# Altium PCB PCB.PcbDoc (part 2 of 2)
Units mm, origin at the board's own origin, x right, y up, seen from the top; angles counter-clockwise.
Board outline 69.72 x 25.78 mm, 2 copper layers (Top Layer, Bottom Layer); 68 components, 49 nets, 251 pads, 101 vias.
Unrouted connection lines stored in the file: 33.
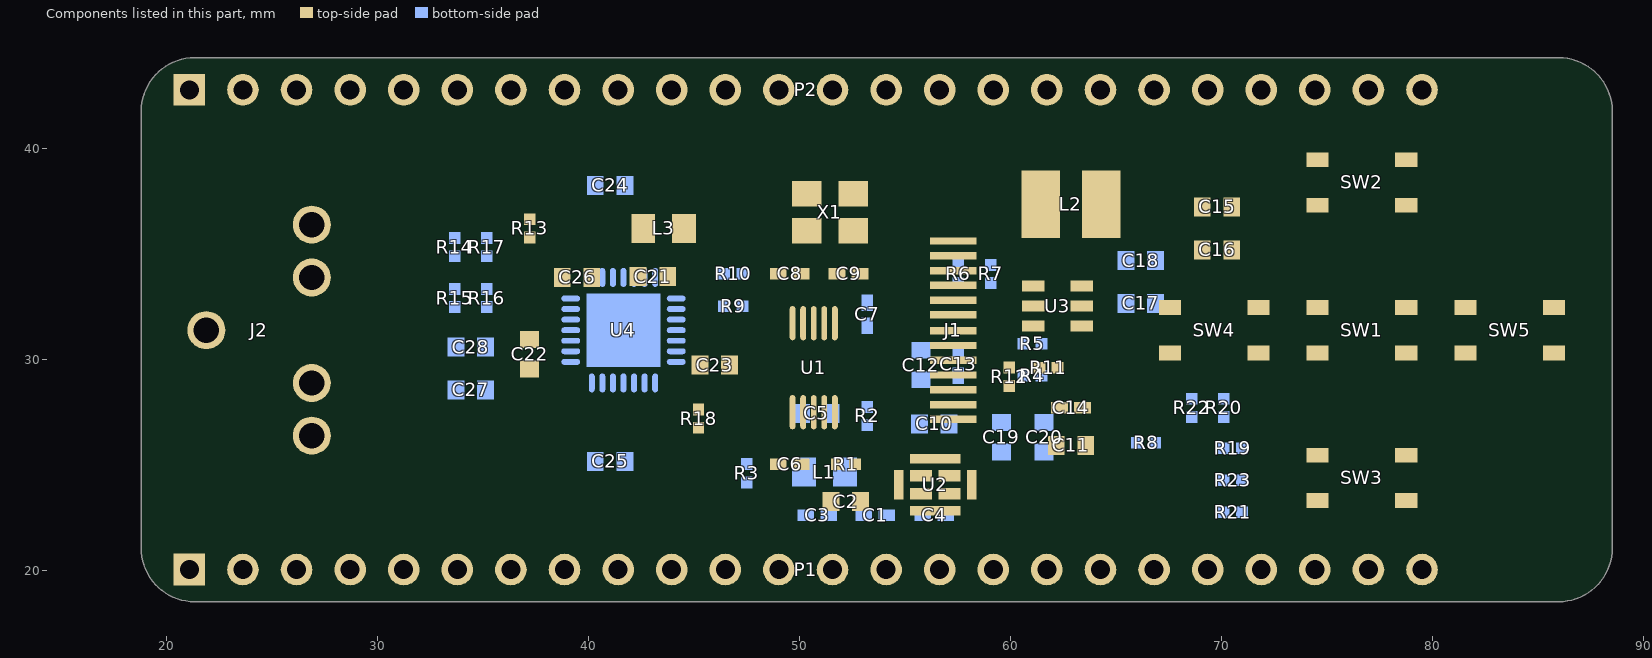
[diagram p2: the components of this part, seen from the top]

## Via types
v1: diameter 0.4, hole 0.25, Top Layer to Bottom Layer, tented both sides, 100 vias
v2: diameter 0.4/0.4 (per signal layer), hole 0.25, Top Layer to Bottom Layer, tented both sides, 1 vias

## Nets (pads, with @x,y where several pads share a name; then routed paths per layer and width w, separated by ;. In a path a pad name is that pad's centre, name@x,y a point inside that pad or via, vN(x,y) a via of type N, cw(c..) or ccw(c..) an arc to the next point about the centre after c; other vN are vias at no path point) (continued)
copper on no net: | length 39.2
  Top Layer w0.013: 84.36,21.761 cw(c84.362,21.776) 84.347,21.776 84.347,22.06 cw(c84.362,22.06) 84.36,22.075 84.638,22.129 ccw(c84.635,22.143) 84.649,22.138 84.746,22.371 ccw(c84.732,22.377) 84.745,22.385 84.585,22.62 cw(c84.598,22.629) 84.587,22.639 84.788,22.84 cw(c84.799,22.829) 84.807,22.842 85.042,22.683 ccw(c85.051,22.695) 85.056,22.681 85.29,22.778 ccw(c85.284,22.792) 85.299,22.789 85.353,23.068 cw(c85.367,23.065) 85.367,23.08 85.651,23.08 cw(c85.651,23.065) 85.666,23.068 85.72,22.789 ccw(c85.735,22.792) 85.729,22.778 85.962,22.681 ccw(c85.968,22.695) 85.976,22.683 86.211,22.842 cw(c86.22,22.829) 86.23,22.84 86.431,22.639 cw(c86.421,22.629) 86.433,22.62 86.274,22.385 ccw(c86.287,22.377) 86.273,22.371 86.369,22.138 ccw(c86.383,22.143) 86.38,22.129 86.659,22.075 cw(c86.656,22.06) 86.671,22.06 86.671,21.776 cw(c86.656,21.776) 86.659,21.761 ; 84.36,21.761 84.638,21.708 cw(c84.635,21.693) 84.649,21.699 84.746,21.465 cw(c84.732,21.459) 84.745,21.451 84.585,21.216 ccw(c84.598,21.208) 84.587,21.197 84.788,20.996 ccw(c84.799,21.007) 84.807,20.994 85.042,21.153 cw(c85.051,21.141) 85.056,21.155 85.163,21.11 ccw(c85.169,21.124) 85.183,21.119 85.38,21.601 ccw(c85.366,21.606) 85.372,21.62 cw(c85.509,21.918) 85.647,21.62 ccw(c85.653,21.606) 85.639,21.601 85.836,21.119 ccw(c85.85,21.124) 85.855,21.11 85.962,21.155 cw(c85.968,21.141) 85.976,21.153 86.211,20.994 ccw(c86.22,21.007) 86.23,20.996 86.431,21.197 ccw(c86.421,21.208) 86.433,21.216 86.274,21.451 cw(c86.287,21.459) 86.273,21.465 86.369,21.699 cw(c86.383,21.693) 86.38,21.708 86.659,21.761 ; 84.386,20.209 84.386,20.458 ccw(c84.493,20.567) 84.423,20.432 ccw(c84.465,20.517) 84.466,20.422 ccw(c84.467,20.541) 84.493,20.425 ccw(c84.473,20.511) 84.515,20.433 ccw(c84.465,20.527) 84.549,20.462 ccw(c84.476,20.518) 84.567,20.501 ccw(c84.341,20.542) 84.57,20.532 ccw(c83.711,20.577) 84.571,20.58 ccw(c83.703,20.584) 84.57,20.629 ccw(c84.343,20.62) 84.567,20.66 ccw(c84.474,20.642) 84.549,20.699 ccw(c84.462,20.631) 84.515,20.728 ccw(c84.473,20.652) 84.493,20.737 ccw(c84.467,20.624) 84.466,20.739 ccw(c84.465,20.634) 84.422,20.73 ccw(c84.468,20.631) 84.386,20.703 84.386,20.736 84.323,20.736 84.323,19.932 84.386,19.932 84.386,20.117 cw(c84.469,20.118) 84.39,20.144 cw(c84.444,20.126) 84.403,20.166 cw(c84.445,20.125) 84.423,20.179 cw(c84.447,20.118) 84.448,20.183 cw(c84.448,20.12) 84.472,20.179 cw(c84.45,20.125) 84.491,20.166 cw(c84.451,20.126) 84.504,20.144 cw(c84.426,20.118) 84.509,20.117 84.509,19.932 84.571,19.932 84.571,20.138 ccw(c84.433,20.139) 84.569,20.163 ccw(c84.467,20.145) 84.563,20.184 ccw(c84.484,20.151) 84.538,20.218 ccw(c84.455,20.119) 84.503,20.239 ccw(c84.468,20.149) 84.468,20.246 ccw(c84.466,20.136) 84.422,20.236 ccw(c84.461,20.152) 84.387,20.209 ; 84.991,20.703 84.991,20.736 84.928,20.736 84.928,20.426 84.991,20.426 84.991,20.61 cw(c85.074,20.612) 84.995,20.638 cw(c85.048,20.62) 85.008,20.659 cw(c85.05,20.619) 85.028,20.673 cw(c85.052,20.611) 85.052,20.677 cw(c85.053,20.614) 85.076,20.673 cw(c85.054,20.619) 85.096,20.659 cw(c85.056,20.62) 85.109,20.638 cw(c85.031,20.612) 85.114,20.61 85.114,20.426 85.176,20.426 85.176,20.632 ccw(c85.037,20.633) 85.174,20.657 ccw(c85.072,20.639) 85.168,20.678 ccw(c85.088,20.645) 85.142,20.712 ccw(c85.059,20.613) 85.108,20.733 ccw(c85.072,20.643) 85.073,20.739 ccw(c85.071,20.629) 85.027,20.73 ccw(c85.065,20.645) 84.992,20.703 ; 85.001,20.209 85.001,20.242 84.939,20.242 84.939,19.932 85.001,19.932 85.001,20.118 cw(c85.085,20.12) 85.006,20.148 cw(c85.05,20.132) 85.02,20.168 cw(c85.062,20.119) 85.062,20.183 cw(c85.062,20.124) 85.083,20.179 cw(c85.053,20.103) 85.103,20.168 85.148,20.222 ccw(c85.075,20.13) 85.117,20.24 ccw(c85.083,20.15) 85.083,20.246 ccw(c85.081,20.136) 85.037,20.236 ccw(c85.076,20.152) 85.003,20.209 ; 85.563,20.025 85.503,20.242 85.437,20.242 85.537,19.932 85.592,19.932 85.657,20.149 ; 85.564,20.025 85.634,20.242 85.68,20.242 85.75,20.025 85.751,20.025 85.811,20.242 85.877,20.242 85.778,19.932 85.723,19.932 85.658,20.149 ; 86.267,20.209 86.267,20.242 86.205,20.242 86.205,19.932 86.267,19.932 86.267,20.118 cw(c86.35,20.12) 86.272,20.148 cw(c86.316,20.132) 86.286,20.168 cw(c86.327,20.119) 86.327,20.183 cw(c86.327,20.124) 86.348,20.179 cw(c86.319,20.103) 86.369,20.168 86.414,20.222 ccw(c86.34,20.13) 86.382,20.24 ccw(c86.349,20.15) 86.349,20.246 ccw(c86.347,20.136) 86.303,20.236 ccw(c86.342,20.152) 86.268,20.209 ; 86.346,20.703 86.346,20.736 86.284,20.736 86.284,20.426 86.346,20.426 86.346,20.612 cw(c86.429,20.614) 86.351,20.642 cw(c86.395,20.626) 86.365,20.662 cw(c86.406,20.613) 86.406,20.677 cw(c86.406,20.618) 86.427,20.673 cw(c86.398,20.597) 86.448,20.662 86.493,20.715 ccw(c86.419,20.623) 86.461,20.733 ccw(c86.428,20.644) 86.428,20.739 ccw(c86.426,20.629) 86.382,20.73 ccw(c86.421,20.645) 86.347,20.703 ; 84.011,20.581 ccw(c84.447,20.578) 84.012,20.537 ccw(c84.17,20.55) 84.018,20.506 ccw(c84.132,20.542) 84.044,20.461 ccw(c84.124,20.533) 84.059,20.448 ccw(c84.16,20.582) 84.079,20.435 ccw(c84.124,20.517) 84.106,20.425 ccw(c84.137,20.581) 84.139,20.422 ccw(c84.14,20.578) 84.171,20.425 ccw(c84.152,20.518) 84.197,20.435 ccw(c84.116,20.584) 84.217,20.448 ccw(c84.153,20.535) 84.233,20.461 ccw(c84.145,20.542) 84.258,20.506 ccw(c84.106,20.55) 84.264,20.537 ccw(c83.826,20.578) 84.266,20.581 ccw(c83.84,20.584) 84.264,20.625 ccw(c84.106,20.611) 84.258,20.655 ccw(c84.145,20.619) 84.233,20.7 ccw(c84.149,20.622) 84.217,20.713 ccw(c84.108,20.566) 84.197,20.727 ccw(c84.152,20.645) 84.171,20.736 ccw(c84.14,20.587) 84.139,20.739 ccw(c84.137,20.584) 84.106,20.736 ccw(c84.124,20.646) 84.079,20.727 ccw(c84.168,20.569) 84.059,20.713 ccw(c84.127,20.624) 84.044,20.7 ccw(c84.132,20.619) 84.018,20.655 ccw(c84.169,20.611) 84.012,20.625 ccw(c84.433,20.584) 84.011,20.581 ; 84.073,20.581 ccw(c84.527,20.579) 84.074,20.552 ccw(c84.201,20.558) 84.076,20.533 ccw(c84.145,20.549) 84.088,20.507 ccw(c84.129,20.535) 84.109,20.49 ccw(c84.137,20.555) 84.139,20.484 ccw(c84.14,20.555) 84.168,20.49 ccw(c84.147,20.536) 84.189,20.507 ccw(c84.124,20.552) 84.201,20.533 ccw(c84.088,20.558) 84.203,20.552 ccw(c83.798,20.578) 84.204,20.58 ccw(c83.795,20.583) 84.203,20.609 ccw(c84.088,20.603) 84.201,20.628 ccw(c84.121,20.608) 84.189,20.654 ccw(c84.147,20.625) 84.168,20.671 ccw(c84.14,20.606) 84.139,20.677 ccw(c84.137,20.606) 84.109,20.671 ccw(c84.129,20.626) 84.088,20.654 ccw(c84.147,20.611) 84.076,20.628 ccw(c84.198,20.603) 84.074,20.609 ccw(c84.504,20.583) 84.073,20.581 ; 84.386,20.58 ccw(c84.628,20.58) 84.395,20.515 ccw(c84.431,20.525) 84.412,20.492 ccw(c84.438,20.537) 84.427,20.486 ccw(c84.446,20.575) 84.447,20.484 ccw(c84.448,20.579) 84.467,20.486 ccw(c84.456,20.538) 84.482,20.492 ccw(c84.464,20.524) 84.5,20.514 ccw(c84.274,20.578) 84.509,20.58 ccw(c84.272,20.583) 84.5,20.647 ccw(c84.464,20.637) 84.482,20.669 ccw(c84.456,20.623) 84.467,20.675 ccw(c84.448,20.583) 84.447,20.677 ccw(c84.446,20.586) 84.427,20.675 ccw(c84.438,20.624) 84.412,20.669 ccw(c84.432,20.636) 84.395,20.646 ccw(c84.63,20.581) 84.386,20.58 ; 84.618,20.579 cw(c84.932,20.581) 84.621,20.621 cw(c84.813,20.597) 84.628,20.656 cw(c84.746,20.618) 84.641,20.684 cw(c84.718,20.636) 84.659,20.705 cw(c84.762,20.585) 84.702,20.731 cw(c84.746,20.621) 84.746,20.739 cw(c84.747,20.611) 84.794,20.731 cw(c84.744,20.607) 84.835,20.704 cw(c84.759,20.62) 84.864,20.662 cw(c84.73,20.611) 84.874,20.608 84.874,20.557 84.68,20.557 ccw(c84.779,20.555) 84.686,20.524 ccw(c84.742,20.543) 84.701,20.5 ccw(c84.748,20.551) 84.725,20.485 ccw(c84.753,20.567) 84.754,20.481 ccw(c84.755,20.57) 84.791,20.488 ccw(c84.748,20.582) 84.822,20.51 84.868,20.472 cw(c84.753,20.569) 84.843,20.449 cw(c84.771,20.546) 84.816,20.433 cw(c84.756,20.583) 84.755,20.422 cw(c84.756,20.57) 84.708,20.43 cw(c84.767,20.602) 84.663,20.453 cw(c84.708,20.518) 84.643,20.472 cw(c84.734,20.536) 84.629,20.5 cw(c84.803,20.56) 84.621,20.536 cw(c84.933,20.578) 84.618,20.579 ; 84.624,20.022 cw(c84.724,20.023) 84.63,20.057 cw(c84.713,20.026) 84.649,20.087 cw(c84.706,20.033) 84.68,20.107 cw(c84.721,19.986) 84.722,20.114 84.806,20.114 84.806,20.147 ccw(c84.767,20.148) 84.802,20.165 ccw(c84.774,20.15) 84.791,20.177 ccw(c84.762,20.13) 84.771,20.185 ccw(c84.748,20.06) 84.744,20.187 ccw(c84.743,20.04) 84.724,20.186 ccw(c84.735,20.1) 84.708,20.182 ccw(c84.726,20.141) 84.687,20.163 84.639,20.2 cw(c84.726,20.137) 84.682,20.235 cw(c84.731,20.124) 84.71,20.243 cw(c84.738,20.084) 84.741,20.245 cw(c84.746,20.038) 84.792,20.24 cw(c84.764,20.117) 84.832,20.223 cw(c84.79,20.163) 84.858,20.191 cw(c84.762,20.151) 84.864,20.169 cw(c84.712,20.142) 84.867,20.143 84.867,19.931 84.806,19.931 84.806,19.958 84.805,19.958 cw(c84.76,19.981) 84.779,19.935 cw(c84.744,20.022) 84.758,19.929 cw(c84.732,20.1) 84.73,19.927 cw(c84.731,20.072) 84.685,19.934 cw(c84.713,20.015) 84.653,19.954 cw(c84.711,20.019) 84.631,19.984 cw(c84.718,20.02) 84.624,20.022 ; 84.68,20.608 cw(c84.78,20.607) 84.686,20.639 cw(c84.744,20.619) 84.7,20.662 cw(c84.743,20.62) 84.721,20.676 cw(c84.745,20.613) 84.746,20.681 cw(c84.747,20.615) 84.771,20.676 cw(c84.748,20.62) 84.792,20.662 cw(c84.747,20.618) 84.806,20.639 cw(c84.71,20.606) 84.811,20.608 84.68,20.608 ; 84.681,20.025 ccw(c84.713,20.024) 84.684,20.01 ccw(c84.72,20.029) 84.695,19.998 ccw(c84.722,20.029) 84.712,19.989 ccw(c84.736,20.083) 84.738,19.986 ccw(c84.743,20.164) 84.771,19.988 ccw(c84.763,20.046) 84.792,19.995 ccw(c84.778,20.014) 84.798,20.001 ccw(c84.766,20.022) 84.803,20.011 ccw(c84.71,20.037) 84.806,20.04 84.806,20.062 84.733,20.062 ccw(c84.735,19.956) 84.71,20.059 ccw(c84.721,20.012) 84.694,20.052 ccw(c84.711,20.028) 84.684,20.041 ccw(c84.717,20.026) 84.681,20.025 ; 85.152,20.087 cw(c86.03,20.091) 85.153,20.135 cw(c85.386,20.126) 85.157,20.166 cw(c85.246,20.149) 85.174,20.205 cw(c85.258,20.141) 85.208,20.234 cw(c85.25,20.158) 85.231,20.243 cw(c85.256,20.128) 85.257,20.246 cw(c85.259,20.154) 85.301,20.235 cw(c85.223,20.089) 85.337,20.209 85.337,20.367 85.4,20.367 85.4,19.932 85.337,19.932 85.337,19.964 cw(c85.255,20.037) 85.301,19.937 cw(c85.258,20.034) 85.257,19.928 cw(c85.256,20.049) 85.231,19.931 cw(c85.25,20.017) 85.208,19.939 cw(c85.255,20.029) 85.174,19.968 cw(c85.244,20.023) 85.157,20.007 cw(c85.392,20.048) 85.153,20.038 cw(c86.053,20.083) 85.152,20.087 ; 85.215,20.087 ccw(c85.452,20.085) 85.223,20.02 ccw(c85.259,20.03) 85.241,19.998 ccw(c85.267,20.045) 85.256,19.992 ccw(c85.275,20.086) 85.276,19.99 ccw(c85.277,20.079) 85.296,19.992 ccw(c85.285,20.042) 85.311,19.998 ccw(c85.291,20.031) 85.329,20.022 ccw(c85.096,20.086) 85.337,20.087 ccw(c85.1,20.088) 85.329,20.152 ccw(c85.291,20.142) 85.311,20.175 ccw(c85.285,20.131) 85.296,20.181 ccw(c85.277,20.094) 85.276,20.183 ccw(c85.275,20.088) 85.256,20.181 ccw(c85.267,20.129) 85.241,20.176 ccw(c85.259,20.143) 85.223,20.153 ccw(c85.448,20.089) 85.215,20.087 ; 85.349,20.477 ccw(c85.491,20.627) 85.412,20.436 ccw(c85.484,20.615) 85.485,20.422 ccw(c85.487,20.611) 85.535,20.428 ccw(c85.499,20.565) 85.577,20.447 ccw(c85.532,20.516) 85.605,20.477 ccw(c85.529,20.516) 85.614,20.517 ccw(c85.506,20.518) 85.609,20.552 ccw(c85.519,20.522) 85.593,20.581 ccw(c85.539,20.537) 85.565,20.601 ccw(c85.524,20.505) 85.546,20.607 ccw(c85.514,20.457) 85.524,20.61 85.473,20.614 cw(c85.477,20.7) 85.453,20.617 cw(c85.461,20.647) 85.44,20.624 cw(c85.462,20.647) 85.434,20.633 cw(c85.455,20.643) 85.432,20.643 cw(c85.466,20.644) 85.443,20.67 cw(c85.467,20.641) 85.459,20.678 cw(c85.483,20.577) 85.485,20.681 cw(c85.487,20.564) 85.53,20.673 cw(c85.45,20.48) 85.568,20.652 85.606,20.697 ccw(c85.486,20.553) 85.554,20.728 ccw(c85.498,20.583) 85.522,20.737 ccw(c85.486,20.507) 85.485,20.739 ccw(c85.483,20.579) 85.439,20.733 ccw(c85.473,20.619) 85.402,20.715 ccw(c85.447,20.653) 85.377,20.685 ccw(c85.467,20.646) 85.369,20.644 ccw(c85.463,20.642) 85.375,20.608 ccw(c85.441,20.635) 85.395,20.581 ccw(c85.459,20.654) 85.423,20.564 ccw(c85.466,20.675) 85.459,20.556 85.513,20.551 cw(c85.508,20.476) 85.53,20.548 cw(c85.519,20.512) 85.542,20.542 cw(c85.527,20.522) 85.549,20.532 cw(c85.522,20.521) 85.551,20.52 cw(c85.518,20.52) 85.547,20.503 cw(c85.517,20.521) 85.534,20.491 cw(c85.499,20.552) 85.514,20.483 cw(c85.491,20.589) 85.49,20.481 cw(c85.489,20.62) 85.437,20.49 cw(c85.49,20.619) 85.392,20.52 85.349,20.477 ; 85.653,20.581 ccw(c86.089,20.578) 85.654,20.537 ccw(c85.812,20.55) 85.66,20.506 ccw(c85.774,20.542) 85.686,20.461 ccw(c85.766,20.533) 85.701,20.448 ccw(c85.802,20.582) 85.721,20.435 ccw(c85.766,20.517) 85.748,20.425 ccw(c85.779,20.581) 85.78,20.422 ccw(c85.782,20.578) 85.813,20.425 ccw(c85.794,20.518) 85.839,20.435 ccw(c85.758,20.584) 85.859,20.448 ccw(c85.795,20.535) 85.875,20.461 ccw(c85.787,20.542) 85.9,20.506 ccw(c85.748,20.55) 85.906,20.537 ccw(c85.468,20.578) 85.908,20.581 ccw(c85.482,20.584) 85.906,20.625 ccw(c85.748,20.611) 85.9,20.655 ccw(c85.787,20.619) 85.875,20.7 ccw(c85.791,20.622) 85.859,20.713 ccw(c85.75,20.566) 85.839,20.727 ccw(c85.794,20.645) 85.813,20.736 ccw(c85.782,20.587) 85.78,20.739 ccw(c85.779,20.584) 85.748,20.736 ccw(c85.766,20.646) 85.721,20.727 ccw(c85.81,20.569) 85.701,20.713 ccw(c85.769,20.624) 85.686,20.7 ccw(c85.774,20.619) 85.66,20.655 ccw(c85.811,20.611) 85.654,20.625 ccw(c86.075,20.584) 85.653,20.581 ; 85.715,20.581 ccw(c86.169,20.579) 85.716,20.552 ccw(c85.843,20.558) 85.718,20.533 ccw(c85.787,20.549) 85.73,20.507 ccw(c85.771,20.535) 85.751,20.49 ccw(c85.779,20.555) 85.78,20.484 ccw(c85.782,20.555) 85.81,20.49 ccw(c85.789,20.536) 85.831,20.507 ccw(c85.766,20.552) 85.843,20.533 ccw(c85.73,20.558) 85.845,20.552 ccw(c85.44,20.578) 85.846,20.58 ccw(c85.437,20.583) 85.845,20.609 ccw(c85.73,20.603) 85.843,20.628 ccw(c85.763,20.608) 85.831,20.654 ccw(c85.789,20.625) 85.81,20.671 ccw(c85.782,20.606) 85.78,20.677 ccw(c85.779,20.606) 85.751,20.671 ccw(c85.771,20.626) 85.73,20.654 ccw(c85.789,20.611) 85.718,20.628 ccw(c85.84,20.603) 85.716,20.609 ccw(c86.146,20.583) 85.715,20.581 ; 85.889,20.022 cw(c85.989,20.023) 85.895,20.057 cw(c85.978,20.026) 85.914,20.087 cw(c85.97,20.033) 85.944,20.107 cw(c85.986,19.986) 85.987,20.114 86.071,20.114 86.071,20.147 ccw(c86.032,20.148) 86.067,20.165 ccw(c86.038,20.15) 86.055,20.177 ccw(c86.026,20.13) 86.036,20.185 ccw(c86.013,20.06) 86.009,20.187 ccw(c86.008,20.04) 85.989,20.186 ccw(c86,20.1) 85.973,20.182 ccw(c85.99,20.141) 85.952,20.163 85.904,20.2 cw(c85.99,20.137) 85.947,20.235 cw(c85.995,20.124) 85.974,20.243 cw(c86.002,20.084) 86.006,20.245 cw(c86.01,20.038) 86.057,20.24 cw(c86.028,20.117) 86.097,20.223 cw(c86.054,20.163) 86.122,20.191 cw(c86.026,20.151) 86.129,20.169 cw(c85.977,20.142) 86.131,20.143 86.131,19.931 86.071,19.931 86.071,19.958 86.069,19.958 cw(c86.025,19.981) 86.043,19.935 cw(c86.008,20.022) 86.022,19.929 cw(c85.996,20.1) 85.995,19.927 cw(c85.996,20.072) 85.95,19.934 cw(c85.977,20.015) 85.917,19.954 cw(c85.976,20.019) 85.896,19.984 cw(c85.983,20.02) 85.889,20.022 ; 85.945,20.025 ccw(c85.977,20.024) 85.949,20.01 ccw(c85.984,20.029) 85.959,19.998 ccw(c85.987,20.029) 85.977,19.989 ccw(c86.001,20.083) 86.003,19.986 ccw(c86.008,20.164) 86.035,19.988 ccw(c86.027,20.046) 86.056,19.995 ccw(c86.043,20.014) 86.063,20.001 ccw(c86.031,20.022) 86.067,20.011 ccw(c85.975,20.037) 86.071,20.04 86.071,20.062 85.998,20.062 ccw(c86,19.956) 85.975,20.059 ccw(c85.986,20.012) 85.958,20.052 ccw(c85.975,20.028) 85.948,20.041 ccw(c85.981,20.026) 85.945,20.025 ; 85.965,20.53 ccw(c86.105,20.529) 85.967,20.505 ccw(c86.069,20.523) 85.973,20.483 ccw(c86.052,20.516) 85.999,20.449 ccw(c86.08,20.548) 86.033,20.429 ccw(c86.069,20.521) 86.069,20.422 ccw(c86.071,20.531) 86.115,20.431 ccw(c86.076,20.516) 86.149,20.458 86.15,20.458 86.15,20.426 86.213,20.426 86.213,20.736 86.15,20.736 86.15,20.551 cw(c86.067,20.549) 86.146,20.523 cw(c86.093,20.541) 86.133,20.502 cw(c86.091,20.543) 86.113,20.488 cw(c86.09,20.548) 86.089,20.484 cw(c86.088,20.55) 86.065,20.488 cw(c86.086,20.542) 86.045,20.502 cw(c86.084,20.541) 86.032,20.523 cw(c86.111,20.549) 86.027,20.551 86.027,20.736 85.965,20.736 85.965,20.53 ; 86.418,20.086 cw(c86.731,20.087) 86.42,20.127 cw(c86.612,20.103) 86.428,20.162 cw(c86.546,20.125) 86.441,20.19 cw(c86.517,20.142) 86.459,20.211 cw(c86.561,20.092) 86.501,20.237 cw(c86.546,20.128) 86.546,20.246 cw(c86.547,20.117) 86.593,20.237 cw(c86.544,20.113) 86.635,20.21 cw(c86.558,20.126) 86.664,20.169 cw(c86.529,20.117) 86.673,20.115 86.673,20.063 86.48,20.063 ccw(c86.578,20.061) 86.485,20.03 ccw(c86.541,20.049) 86.501,20.006 ccw(c86.548,20.057) 86.525,19.991 ccw(c86.553,20.073) 86.554,19.987 ccw(c86.554,20.076) 86.59,19.994 ccw(c86.548,20.088) 86.622,20.017 86.667,19.978 cw(c86.553,20.075) 86.643,19.955 cw(c86.57,20.052) 86.615,19.94 cw(c86.556,20.09) 86.555,19.928 cw(c86.555,20.076) 86.508,19.936 cw(c86.567,20.108) 86.462,19.959 cw(c86.508,20.024) 86.443,19.979 cw(c86.534,20.042) 86.429,20.006 cw(c86.603,20.066) 86.42,20.042 cw(c86.733,20.084) 86.418,20.086 ; 86.48,20.115 cw(c86.579,20.113) 86.485,20.146 cw(c86.543,20.125) 86.499,20.168 cw(c86.543,20.126) 86.52,20.182 cw(c86.545,20.119) 86.546,20.187 cw(c86.546,20.121) 86.571,20.182 cw(c86.548,20.126) 86.591,20.168 cw(c86.546,20.125) 86.605,20.146 cw(c86.51,20.112) 86.611,20.115 86.48,20.115 ; 86.487,20.58 cw(c86.757,20.582) 86.489,20.62 cw(c86.666,20.595) 86.498,20.653 cw(c86.616,20.612) 86.511,20.681 cw(c86.597,20.624) 86.53,20.703 cw(c86.633,20.584) 86.576,20.73 cw(c86.627,20.596) 86.627,20.739 cw(c86.628,20.597) 86.661,20.736 cw(c86.633,20.617) 86.691,20.724 cw(c86.608,20.572) 86.739,20.686 86.693,20.645 ccw(c86.621,20.588) 86.664,20.669 ccw(c86.63,20.603) 86.63,20.677 ccw(c86.628,20.582) 86.594,20.671 ccw(c86.617,20.613) 86.569,20.653 ccw(c86.631,20.603) 86.554,20.623 ccw(c86.708,20.583) 86.549,20.58 ccw(c86.706,20.578) 86.554,20.538 ccw(c86.631,20.558) 86.569,20.508 ccw(c86.617,20.548) 86.594,20.49 ccw(c86.628,20.579) 86.63,20.484 ccw(c86.63,20.558) 86.664,20.492 ccw(c86.621,20.572) 86.693,20.517 86.739,20.475 cw(c86.61,20.588) 86.691,20.437 cw(c86.633,20.545) 86.661,20.426 cw(c86.628,20.566) 86.627,20.422 cw(c86.627,20.566) 86.576,20.431 cw(c86.633,20.578) 86.53,20.459 cw(c86.595,20.536) 86.511,20.48 cw(c86.615,20.548) 86.498,20.507 cw(c86.665,20.566) 86.489,20.541 cw(c86.756,20.579) 86.487,20.58 ; 86.757,20.579 cw(c87.071,20.581) 86.76,20.621 cw(c86.952,20.597) 86.768,20.656 cw(c86.885,20.618) 86.781,20.684 cw(c86.857,20.636) 86.799,20.705 cw(c86.901,20.585) 86.841,20.731 cw(c86.885,20.621) 86.885,20.739 cw(c86.886,20.611) 86.933,20.731 cw(c86.883,20.607) 86.975,20.704 cw(c86.898,20.62) 87.003,20.662 cw(c86.869,20.611) 87.013,20.608 87.013,20.557 86.82,20.557 ccw(c86.918,20.555) 86.825,20.524 ccw(c86.881,20.543) 86.84,20.5 ccw(c86.888,20.551) 86.864,20.485 ccw(c86.893,20.567) 86.894,20.481 ccw(c86.894,20.57) 86.93,20.488 ccw(c86.887,20.582) 86.962,20.51 87.007,20.472 cw(c86.893,20.569) 86.982,20.449 cw(c86.91,20.546) 86.955,20.433 cw(c86.895,20.583) 86.895,20.422 cw(c86.895,20.57) 86.848,20.43 cw(c86.907,20.602) 86.802,20.453 cw(c86.848,20.518) 86.783,20.472 cw(c86.874,20.536) 86.769,20.5 cw(c86.943,20.56) 86.76,20.536 cw(c87.072,20.578) 86.757,20.579 ; 86.82,20.608 cw(c86.919,20.607) 86.825,20.639 cw(c86.883,20.619) 86.839,20.662 cw(c86.883,20.62) 86.86,20.676 cw(c86.884,20.613) 86.885,20.681 cw(c86.886,20.615) 86.91,20.676 cw(c86.887,20.62) 86.931,20.662 cw(c86.886,20.618) 86.945,20.639 cw(c86.849,20.606) 86.951,20.608 86.82,20.608

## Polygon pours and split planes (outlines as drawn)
no net on Top Overlay "NONET_L-01_P-001" (solid): 84.004,40.31 84.074,40.195 84.155,40.087 84.245,39.988 84.344,39.897 84.452,39.817 84.567,39.747 84.689,39.688 84.818,39.641 84.952,39.607 85.091,39.585 85.234,39.578 85.377,39.585 85.515,39.607 85.649,39.641 85.778,39.688 85.9,39.747 86.015,39.817 86.123,39.897 86.222,39.988 86.313,40.087 86.393,40.195 86.463,40.31 86.522,40.432 86.569,40.561 86.603,40.695 86.625,40.833 86.632,40.976 86.625,41.119 86.603,41.258 86.569,41.392 86.522,41.521 86.463,41.643 86.393,41.758 86.313,41.866 86.222,41.965 86.123,42.055 86.015,42.136 85.9,42.206 85.778,42.265 85.649,42.312 85.515,42.346 85.377,42.367 85.234,42.375 85.091,42.367 84.952,42.346 84.818,42.312 84.689,42.265 84.567,42.206 84.452,42.136 84.344,42.055 84.245,41.965 84.155,41.866 84.074,41.758 84.004,41.643 83.945,41.521 83.898,41.392 83.864,41.258 83.843,41.119 83.835,40.976 83.843,40.833 83.864,40.695 83.898,40.561 83.945,40.432
no net on Top Overlay "NONET_L-01_P-001" (none): 84.897,39.141 84.891,39.16 84.891,39.183 84.9,39.21 84.919,39.23 84.953,39.244 84.923,39.276 84.917,39.315 84.934,39.354 84.974,39.378 85.022,39.381 85.056,39.372 85.081,39.355 85.094,39.334 85.096,39.309 85.081,39.278 85.045,39.256 85.071,39.239 85.086,39.22 85.093,39.2 85.092,39.176 85.077,39.135 85.05,39.109 85.012,39.096 84.971,39.096 84.927,39.111
no net on Top Overlay "NONET_L-01_P-001" (solid): 86.591,41.848 86.604,41.856 86.598,41.868 86.595,41.88 86.596,41.892 86.604,41.901 86.673,41.945 86.679,41.937 86.655,41.869 86.625,41.796 86.681,41.708 86.694,41.717 86.689,41.725 86.685,41.736 86.686,41.758 86.693,41.782 86.711,41.836 86.728,41.883 86.753,41.865 86.777,41.856 86.801,41.856 86.825,41.867 86.845,41.888 86.851,41.915 86.844,41.949 86.823,41.989 86.74,42.117 86.728,42.109 86.733,42.096 86.737,42.082 86.736,42.069 86.727,42.061 86.567,41.957 86.555,41.953 86.543,41.957 86.534,41.966 86.525,41.978 86.512,41.97
no net on Top Overlay "NONET_L-01_P-001" (solid): 85.871,39.265 85.883,39.246 85.899,39.233 85.94,39.222 85.985,39.233 86.02,39.254 86.045,39.285 86.055,39.321 86.047,39.364 86.035,39.385 86.019,39.398 85.996,39.406 85.966,39.408 85.985,39.445 85.982,39.48 85.967,39.5 85.945,39.511 85.915,39.513 85.881,39.503 85.841,39.475 85.82,39.434 85.825,39.392 85.851,39.362 85.893,39.35 85.871,39.32 85.865,39.293
no net on Top Overlay "NONET_L-01_P-001" (none): 85.409,39.097 85.428,39.086 85.471,39.098 85.509,39.12 85.539,39.151 85.561,39.188 85.571,39.23 85.57,39.28 85.562,39.316 85.548,39.343 85.53,39.363 85.509,39.376 85.484,39.382 85.455,39.382 85.426,39.374 85.403,39.361 85.385,39.342 85.374,39.32 85.369,39.267 85.379,39.235 85.398,39.212 85.421,39.2 85.449,39.198 85.481,39.208 85.514,39.241 85.512,39.198 85.504,39.166 85.488,39.138 85.462,39.116 85.43,39.106 85.413,39.106
no net on Top Overlay "NONET_L-01_P-001" (none): 85.409,39.097 85.428,39.086 85.471,39.098 85.509,39.12 85.539,39.151 85.561,39.188 85.571,39.23 85.57,39.28 85.562,39.316 85.548,39.343 85.53,39.363 85.509,39.376 85.484,39.382 85.455,39.382 85.426,39.374 85.403,39.361 85.385,39.342 85.374,39.32 85.369,39.267 85.379,39.235 85.398,39.212 85.421,39.2 85.449,39.198 85.481,39.208 85.514,39.241 85.512,39.198 85.504,39.166 85.488,39.138 85.462,39.116 85.43,39.106 85.413,39.106
no net on Top Overlay "NONET_L-01_P-001" (solid): 83.531,40.194 83.529,40.207 83.527,40.222 83.531,40.234 83.541,40.241 83.72,40.309 83.732,40.311 83.743,40.304 83.75,40.293 83.756,40.28 83.77,40.285 83.718,40.424 83.704,40.418 83.707,40.404 83.708,40.391 83.704,40.379 83.694,40.372 83.623,40.345 83.615,40.365 83.593,40.41 83.565,40.441 83.53,40.455 83.49,40.45 83.464,40.433 83.452,40.407 83.451,40.373 83.464,40.328 83.517,40.189
no net on Top Overlay "NONET_L-01_P-001" (solid): 84.897,39.141 84.891,39.16 84.891,39.183 84.9,39.21 84.919,39.23 84.953,39.244 84.923,39.276 84.917,39.315 84.934,39.354 84.974,39.378 85.022,39.381 85.056,39.372 85.081,39.355 85.094,39.334 85.096,39.309 85.081,39.278 85.045,39.256 85.071,39.239 85.086,39.22 85.093,39.2 85.092,39.176 85.077,39.135 85.05,39.109 85.012,39.096 84.971,39.096 84.927,39.111
no net on Top Overlay "NONET_L-01_P-001" (solid): 85.409,39.097 85.428,39.086 85.471,39.098 85.509,39.12 85.539,39.151 85.561,39.188 85.571,39.23 85.57,39.28 85.562,39.316 85.548,39.343 85.53,39.363 85.509,39.376 85.484,39.382 85.455,39.382 85.426,39.374 85.403,39.361 85.385,39.342 85.374,39.32 85.369,39.267 85.379,39.235 85.398,39.212 85.421,39.2 85.449,39.198 85.481,39.208 85.514,39.241 85.512,39.198 85.504,39.166 85.488,39.138 85.462,39.116 85.43,39.106 85.413,39.106
no net on Bottom Layer "NONET_L02_P004" (none, pour order 4): 84.004,40.31 84.074,40.195 84.155,40.087 84.245,39.988 84.344,39.897 84.452,39.817 84.567,39.747 84.689,39.688 84.818,39.641 84.952,39.607 85.091,39.585 85.234,39.578 85.377,39.585 85.515,39.607 85.649,39.641 85.778,39.688 85.9,39.747 86.015,39.817 86.123,39.897 86.222,39.988 86.313,40.087 86.393,40.195 86.463,40.31 86.522,40.432 86.569,40.561 86.603,40.695 86.625,40.833 86.632,40.976 86.625,41.119 86.603,41.258 86.569,41.392 86.522,41.521 86.463,41.643 86.393,41.758 86.313,41.866 86.222,41.965 86.123,42.055 86.015,42.136 85.9,42.206 85.778,42.265 85.649,42.312 85.515,42.346 85.377,42.367 85.234,42.375 85.091,42.367 84.952,42.346 84.818,42.312 84.689,42.265 84.567,42.206 84.452,42.136 84.344,42.055 84.245,41.965 84.155,41.866 84.074,41.758 84.004,41.643 83.945,41.521 83.898,41.392 83.864,41.258 83.843,41.119 83.835,40.976 83.843,40.833 83.864,40.695 83.898,40.561 83.945,40.432
no net on Bottom Layer "NONET_L02_P005" (none, pour order 5): 84.004,40.31 84.074,40.195 84.155,40.087 84.245,39.988 84.344,39.897 84.452,39.817 84.567,39.747 84.689,39.688 84.818,39.641 84.952,39.607 85.091,39.585 85.234,39.578 85.377,39.585 85.515,39.607 85.649,39.641 85.778,39.688 85.9,39.747 86.015,39.817 86.123,39.897 86.222,39.988 86.313,40.087 86.393,40.195 86.463,40.31 86.522,40.432 86.569,40.561 86.603,40.695 86.625,40.833 86.632,40.976 86.625,41.119 86.603,41.258 86.569,41.392 86.522,41.521 86.463,41.643 86.393,41.758 86.313,41.866 86.222,41.965 86.123,42.055 86.015,42.136 85.9,42.206 85.778,42.265 85.649,42.312 85.515,42.346 85.377,42.367 85.234,42.375 85.091,42.367 84.952,42.346 84.818,42.312 84.689,42.265 84.567,42.206 84.452,42.136 84.344,42.055 84.245,41.965 84.155,41.866 84.074,41.758 84.004,41.643 83.945,41.521 83.898,41.392 83.864,41.258 83.843,41.119 83.835,40.976 83.843,40.833 83.864,40.695 83.898,40.561 83.945,40.432
GND on Bottom Layer "GND_L02_P003" (solid, remove dead copper, pour order 3): 21.336,18.542 cw(c21.336,21.082) 18.796,21.082 18.796,41.783 cw(c21.336,41.783) 21.336,44.323 85.979,44.323 cw(c85.979,41.783) 88.519,41.783 88.519,21.082 cw(c85.979,21.082) 85.979,18.542

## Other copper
Top Layer:
  region: 84.687,20.163
  region: 85.952,20.163 85.951,20.163
  region: 85.781,20.479 85.78,20.479
  region: 84.139,20.479 84.138,20.479
  region: 86.695,20.515 86.693,20.517
  region: 84.212,20.58 84.204,20.58 84.212,20.58
  region: 85.854,20.58 85.846,20.58 85.854,20.58
  region: 84.139,20.682 84.138,20.682 84.139,20.682
  region: 85.781,20.682 85.78,20.682 85.781,20.682
  region: 84.493,20.738 84.515,20.728 84.515,20.729 84.547,20.716 84.552,20.702 84.552,20.701 84.569,20.66 84.567,20.66 84.573,20.629 84.579,20.584 84.578,20.58 84.579,20.577 84.573,20.532 84.567,20.501 84.569,20.501 84.552,20.46 84.546,20.446 84.515,20.433 84.493,20.423 84.467,20.412 84.466,20.413 84.466,20.415 84.465,20.414 84.422,20.432 84.422,20.431 84.386,20.446 84.386,20.215 84.389,20.223 84.422,20.236 84.466,20.255 84.468,20.254 84.468,20.253 84.503,20.239 84.542,20.223 84.54,20.221 84.549,20.217 84.563,20.184 84.572,20.163 84.583,20.139 84.582,20.138 84.571,20.138 84.571,19.932 84.509,19.932 84.515,20.116 84.516,20.118 84.505,20.145 84.495,20.169 84.494,20.169 84.472,20.179 84.448,20.188 84.447,20.189 84.423,20.179 84.4,20.169 84.39,20.145 84.379,20.118 84.38,20.116 84.386,20.117 84.386,19.932 84.323,19.932 84.323,20.736 84.386,20.736 84.381,20.707 84.384,20.715 84.422,20.73 84.465,20.748 84.466,20.748 84.466,20.749 84.467,20.749 hole: 84.448,20.685 84.447,20.684 84.447,20.684 84.446,20.685 84.427,20.677 84.427,20.676 84.412,20.67 84.412,20.67 84.402,20.666 84.394,20.646 84.394,20.646 84.381,20.581 84.381,20.58 84.381,20.58 84.381,20.58 84.394,20.515 84.394,20.515 84.402,20.496 84.412,20.492 84.412,20.492 84.427,20.485 84.427,20.485 84.446,20.477 84.447,20.477 84.447,20.477 84.448,20.476 84.467,20.484 84.467,20.485 84.483,20.491 84.483,20.491 84.493,20.496 84.5,20.514 84.501,20.514 84.513,20.578 84.513,20.58 84.513,20.58 84.513,20.583 84.501,20.647 84.5,20.647 84.493,20.666 84.483,20.67 84.483,20.67 84.467,20.676 84.467,20.677 hole: 84.386,20.458 84.377,20.45 84.386,20.446 hole: 84.386,20.215 84.384,20.211 84.386,20.209
  region: 85.4,19.932 85.337,19.932 85.342,19.96 85.34,19.953 85.301,19.937 85.258,19.919 85.257,19.92 85.257,19.919 85.256,19.918 85.23,19.929 85.23,19.93 85.208,19.939 85.178,19.951 85.172,19.966 85.155,20.007 85.157,20.007 85.15,20.038 85.144,20.083 85.145,20.087 85.145,20.091 85.15,20.136 85.157,20.166 85.155,20.167 85.172,20.207 85.171,20.208 85.177,20.222 85.208,20.235 85.23,20.244 85.256,20.255 85.257,20.255 85.257,20.253 85.259,20.253 85.301,20.236 85.337,20.212 85.337,20.367 85.4,20.367 hole: 85.275,20.191 85.256,20.183 85.256,20.182 85.241,20.176 85.241,20.176 85.231,20.172 85.223,20.153 85.223,20.153 85.21,20.089 85.21,20.087 85.21,20.087 85.21,20.087 85.21,20.087 85.21,20.085 85.223,20.02 85.223,20.02 85.231,20.002 85.241,19.998 85.241,19.998 85.256,19.991 85.256,19.99 85.275,19.982 85.276,19.983 85.276,19.983 85.277,19.983 85.296,19.991 85.296,19.991 85.311,19.998 85.311,19.998 85.321,20.002 85.329,20.022 85.329,20.021 85.342,20.086 85.342,20.087 85.342,20.087 85.342,20.088 85.329,20.152 85.329,20.152 85.321,20.172 85.311,20.176 85.311,20.176 85.296,20.182 85.296,20.183 85.277,20.191 85.276,20.19 85.276,20.191
  region: 85.814,20.739 85.813,20.738 85.839,20.727 85.86,20.714 85.861,20.716 85.879,20.709 85.88,20.705 85.901,20.656 85.907,20.625 85.908,20.625 85.917,20.584 85.916,20.581 85.917,20.578 85.909,20.537 85.907,20.537 85.901,20.506 85.88,20.456 85.88,20.457 85.878,20.452 85.861,20.445 85.86,20.447 85.839,20.434 85.813,20.423 85.813,20.425 85.782,20.419 85.78,20.419 85.781,20.419 85.779,20.419 85.748,20.425 85.747,20.423 85.721,20.434 85.701,20.447 85.699,20.445 85.684,20.451 85.681,20.457 85.68,20.456 85.66,20.506 85.654,20.537 85.652,20.537 85.644,20.578 85.645,20.581 85.644,20.584 85.652,20.625 85.654,20.625 85.66,20.656 85.68,20.705 85.681,20.705 85.683,20.71 85.699,20.716 85.701,20.714 85.721,20.727 85.747,20.738 85.748,20.736 85.779,20.742 85.781,20.742 85.78,20.751 85.782,20.752 hole: 85.779,20.683 85.751,20.671 85.751,20.671 85.733,20.664 85.729,20.655 85.729,20.655 85.717,20.628 85.716,20.628 85.708,20.61 85.712,20.61 85.707,20.583 85.707,20.581 85.707,20.581 85.706,20.579 85.712,20.552 85.708,20.552 85.716,20.533 85.717,20.533 85.729,20.506 85.729,20.506 85.733,20.497 85.751,20.49 85.751,20.49 85.779,20.478 85.781,20.479 85.782,20.478 85.81,20.49 85.81,20.49 85.828,20.497 85.832,20.506 85.832,20.506 85.843,20.533 85.844,20.532 85.852,20.551 85.849,20.551 85.854,20.578 85.854,20.58 85.854,20.58 85.854,20.583 85.849,20.609 85.852,20.61 85.844,20.628 85.843,20.628 85.832,20.655 85.832,20.655 85.828,20.664 85.81,20.671 85.81,20.671 85.782,20.683 85.781,20.682 hole: 85.645,20.581 85.645,20.581 85.653,20.581
  region: 84.172,20.739 84.171,20.738 84.197,20.727 84.218,20.714 84.22,20.716 84.237,20.709 84.238,20.705 84.259,20.656 84.265,20.625 84.266,20.625 84.275,20.584 84.274,20.581 84.275,20.578 84.267,20.537 84.265,20.537 84.259,20.506 84.238,20.456 84.238,20.457 84.236,20.452 84.219,20.445 84.218,20.447 84.197,20.434 84.171,20.423 84.171,20.425 84.14,20.419 84.138,20.419 84.139,20.419 84.137,20.419 84.106,20.425 84.105,20.423 84.079,20.434 84.059,20.447 84.057,20.445 84.042,20.451 84.039,20.457 84.038,20.456 84.018,20.506 84.012,20.537 84.01,20.537 84.002,20.578 84.003,20.581 84.002,20.584 84.01,20.625 84.012,20.625 84.018,20.656 84.038,20.705 84.039,20.705 84.041,20.71 84.057,20.716 84.059,20.714 84.079,20.727 84.105,20.738 84.106,20.736 84.137,20.742 84.139,20.742 84.138,20.751 84.14,20.752 hole: 84.137,20.683 84.109,20.671 84.109,20.671 84.091,20.664 84.087,20.655 84.087,20.655 84.075,20.628 84.074,20.628 84.066,20.61 84.07,20.61 84.065,20.583 84.065,20.581 84.065,20.581 84.064,20.579 84.07,20.552 84.066,20.552 84.074,20.533 84.075,20.533 84.087,20.506 84.087,20.506 84.091,20.497 84.109,20.49 84.109,20.49 84.137,20.478 84.139,20.479 84.14,20.478 84.168,20.49 84.168,20.49 84.186,20.497 84.19,20.506 84.19,20.506 84.201,20.533 84.202,20.532 84.21,20.551 84.207,20.551 84.212,20.578 84.212,20.58 84.212,20.58 84.212,20.583 84.207,20.609 84.21,20.61 84.202,20.628 84.201,20.628 84.19,20.655 84.19,20.655 84.186,20.664 84.168,20.671 84.168,20.671 84.14,20.683 84.139,20.682 hole: 84.003,20.581 84.003,20.581 84.011,20.581
  region: 85.778,19.932 85.723,19.932 85.658,20.149 85.657,20.149 85.592,19.932 85.537,19.932 85.437,20.242 85.503,20.242 85.563,20.025 85.564,20.025 85.634,20.242 85.68,20.242 85.75,20.025 85.751,20.025 85.811,20.242 85.877,20.242
  region: 86.593,20.237 86.641,20.217 86.64,20.216 86.645,20.213 86.664,20.169 86.685,20.117 86.684,20.114 86.673,20.115 86.673,20.063 86.473,20.063 86.472,20.061 86.485,20.03 86.496,20.004 86.498,20.003 86.498,20.002 86.524,19.991 86.553,19.98 86.554,19.98 86.554,19.979 86.59,19.994 86.627,20.009 86.628,20.011 86.622,20.017 86.673,19.973 86.668,19.96 86.646,19.951 86.645,19.952 86.615,19.94 86.616,19.937 86.556,19.925 86.555,19.925 86.555,19.916 86.508,19.936 86.508,19.934 86.496,19.937 86.462,19.959 86.461,19.958 86.447,19.963 86.441,19.977 86.429,20.006 86.427,20.006 86.42,20.042 86.411,20.084 86.412,20.086 86.412,20.087 86.42,20.128 86.427,20.163 86.428,20.162 86.439,20.191 86.44,20.191 86.448,20.211 86.456,20.214 86.458,20.212 86.5,20.24 86.501,20.237 86.546,20.255 86.546,20.256 86.547,20.256 hole: 86.545,20.192 86.52,20.182 86.52,20.182 86.496,20.172 86.496,20.171 86.496,20.172 86.485,20.146 86.485,20.146 86.472,20.115 86.48,20.115 86.618,20.115 86.606,20.146 86.605,20.146 86.595,20.172 86.595,20.171 86.594,20.172 86.571,20.182 86.571,20.182 86.546,20.192 86.546,20.192 86.546,20.192
  region: 84.794,20.731 84.842,20.711 84.84,20.709 84.846,20.707 84.864,20.662 84.886,20.611 84.885,20.608 84.874,20.608 84.874,20.557 84.673,20.557 84.672,20.555 84.685,20.524 84.686,20.524 84.696,20.498 84.699,20.497 84.698,20.496 84.725,20.485 84.753,20.473 84.754,20.474 84.754,20.473 84.755,20.473 84.791,20.488 84.827,20.503 84.828,20.505 84.822,20.51 84.873,20.467 84.868,20.454 84.846,20.445 84.845,20.446 84.816,20.433 84.817,20.431 84.756,20.419 84.755,20.419 84.755,20.41 84.708,20.429 84.708,20.428 84.696,20.43 84.663,20.453 84.662,20.451 84.647,20.457 84.642,20.471 84.641,20.471 84.629,20.5 84.628,20.499 84.62,20.536 84.612,20.578 84.612,20.58 84.612,20.579 84.612,20.581 84.62,20.621 84.627,20.657 84.628,20.656 84.64,20.685 84.649,20.705 84.657,20.708 84.659,20.706 84.7,20.734 84.701,20.734 84.702,20.731 84.746,20.749 84.746,20.75 84.747,20.75 hole: 84.745,20.686 84.721,20.676 84.721,20.676 84.697,20.666 84.696,20.665 84.696,20.665 84.686,20.639 84.686,20.639 84.673,20.609 84.68,20.608 84.819,20.609 84.806,20.639 84.806,20.639 84.795,20.665 84.795,20.665 84.795,20.666 84.771,20.676 84.771,20.676 84.747,20.686 84.746,20.686 84.746,20.686
  region: 86.933,20.731 86.981,20.711 86.98,20.709 86.985,20.707 87.003,20.662 87.025,20.611 87.024,20.608 87.013,20.608 87.013,20.557 86.812,20.557 86.812,20.555 86.825,20.524 86.836,20.498 86.838,20.497 86.837,20.496 86.864,20.485 86.893,20.473 86.894,20.474 86.894,20.473 86.93,20.488 86.966,20.503 86.967,20.505 86.962,20.51 87.013,20.467 87.007,20.454 86.985,20.445 86.985,20.446 86.955,20.433 86.956,20.431 86.895,20.419 86.895,20.41 86.848,20.429 86.847,20.428 86.836,20.43 86.802,20.453 86.801,20.451 86.787,20.457 86.781,20.471 86.78,20.471 86.768,20.5 86.767,20.499 86.76,20.536 86.759,20.536 86.751,20.578 86.751,20.579 86.751,20.58 86.751,20.579 86.751,20.581 86.759,20.621 86.766,20.657 86.767,20.656 86.779,20.685 86.788,20.705 86.796,20.708 86.798,20.706 86.84,20.734 86.841,20.731 86.885,20.749 86.885,20.75 86.886,20.75 hole: 86.884,20.686 86.86,20.676 86.86,20.676 86.836,20.666 86.836,20.665 86.836,20.665 86.825,20.639 86.825,20.639 86.812,20.609 86.82,20.608 86.958,20.609 86.945,20.639 86.945,20.639 86.934,20.665 86.934,20.665 86.934,20.666 86.91,20.676 86.91,20.676 86.886,20.686 86.885,20.686 86.885,20.686
  region: 86.057,20.24 86.057,20.242 86.098,20.225 86.111,20.219 86.122,20.191 86.131,20.17 86.129,20.169 86.134,20.143 86.131,20.143 86.131,19.931 86.071,19.931 86.071,19.958 86.07,19.958 86.063,19.943 86.043,19.935 86.023,19.926 86.022,19.929 85.996,19.924 85.995,19.924 85.995,19.915 85.95,19.934 85.913,19.95 85.914,19.95 85.909,19.952 85.896,19.984 85.881,20.02 85.881,20.022 85.88,20.023 85.895,20.057 85.909,20.091 85.91,20.093 85.944,20.107 85.986,20.124 85.987,20.124 85.987,20.114 86.071,20.114 86.073,20.147 86.074,20.148 86.067,20.165 86.063,20.175 86.056,20.178 86.036,20.186 86.036,20.187 86.013,20.197 86.008,20.195 86.009,20.199 86.008,20.199 85.988,20.191 85.989,20.189 85.973,20.182 85.957,20.175 85.951,20.163 85.901,20.202 85.908,20.219 85.947,20.235 85.974,20.246 85.974,20.243 86.002,20.249 86.006,20.248 86.006,20.249 86.01,20.249 hole: 85.998,20.07 85.974,20.061 85.975,20.06 85.958,20.053 85.958,20.053 85.953,20.051 85.948,20.041 85.948,20.041 85.943,20.026 85.943,20.025 85.943,20.025 85.943,20.024 85.949,20.01 85.949,20.01 85.954,19.998 85.958,19.996 85.958,19.996 85.976,19.988 85.976,19.988 86.001,19.978 86.003,19.978 86.003,19.983 86.008,19.982 86.035,19.987 86.035,19.986 86.057,19.994 86.057,19.994 86.061,19.996 86.063,20.001 86.063,20.001 86.067,20.011 86.068,20.011 86.079,20.037 86.078,20.04 86.071,20.04 86.071,20.062
  region: 84.792,20.24 84.793,20.242 84.833,20.225 84.846,20.219 84.858,20.191 84.867,20.17 84.864,20.169 84.869,20.143 84.867,20.143 84.867,19.931 84.806,19.931 84.806,19.958 84.805,19.958 84.799,19.943 84.779,19.935 84.758,19.926 84.758,19.929 84.732,19.924 84.73,19.924 84.73,19.915 84.685,19.934 84.648,19.95 84.649,19.95 84.645,19.952 84.631,19.984 84.616,20.02 84.617,20.022 84.616,20.022 84.616,20.023 84.63,20.057 84.644,20.091 84.645,20.091 84.646,20.093 84.68,20.107 84.679,20.107 84.721,20.124 84.722,20.124 84.722,20.114 84.806,20.114 84.809,20.147 84.809,20.148 84.802,20.165 84.798,20.175 84.791,20.178 84.772,20.186 84.772,20.187 84.748,20.197 84.744,20.195 84.744,20.199 84.743,20.199 84.724,20.191 84.724,20.189 84.708,20.182 84.692,20.175 84.687,20.163 84.637,20.202 84.644,20.219 84.682,20.235 84.709,20.246 84.71,20.243 84.738,20.249 84.741,20.248 84.741,20.249 84.746,20.249 hole: 84.733,20.07 84.71,20.061 84.71,20.06 84.693,20.053 84.693,20.053 84.688,20.051 84.684,20.041 84.684,20.041 84.678,20.026 84.679,20.025 84.678,20.025 84.678,20.024 84.684,20.01 84.684,20.01 84.689,19.998 84.693,19.996 84.693,19.996 84.712,19.988 84.712,19.988 84.736,19.978 84.738,19.978 84.738,19.983 84.743,19.982 84.771,19.987 84.771,19.986 84.792,19.994 84.792,19.994 84.796,19.996 84.798,20.001 84.799,20.001 84.803,20.011 84.803,20.011 84.814,20.037 84.813,20.04 84.806,20.04 84.806,20.062
  region: 85.523,20.737 85.555,20.73 85.555,20.731 85.559,20.73 85.607,20.698 85.606,20.697 85.568,20.652 85.531,20.676 85.53,20.673 85.487,20.69 85.485,20.689 85.485,20.688 85.483,20.689 85.459,20.679 85.442,20.671 85.442,20.672 85.44,20.671 85.429,20.644 85.429,20.643 85.43,20.643 85.434,20.633 85.438,20.623 85.439,20.623 85.453,20.617 85.472,20.609 85.473,20.614 85.524,20.619 85.547,20.61 85.547,20.609 85.565,20.601 85.592,20.59 85.595,20.582 85.596,20.583 85.609,20.552 85.623,20.518 85.622,20.517 85.62,20.518 85.621,20.516 85.605,20.477 85.595,20.453 85.577,20.446 85.578,20.445 85.535,20.427 85.535,20.428 85.487,20.418 85.485,20.419 85.485,20.418 85.484,20.418 85.411,20.433 85.411,20.432 85.347,20.475 85.349,20.477 85.384,20.512 85.437,20.49 85.489,20.469 85.49,20.47 85.49,20.472 85.491,20.472 85.515,20.481 85.515,20.482 85.534,20.49 85.544,20.494 85.547,20.503 85.554,20.52 85.554,20.521 85.549,20.532 85.546,20.541 85.543,20.542 85.543,20.543 85.53,20.548 85.514,20.555 85.513,20.551 85.458,20.549 85.423,20.564 85.391,20.577 85.392,20.578 85.387,20.58 85.375,20.608 85.361,20.642 85.362,20.644 85.361,20.646 85.377,20.685 85.388,20.712 85.401,20.717 85.4,20.718 85.439,20.734 85.483,20.743 85.485,20.742 85.485,20.744 85.486,20.744
  region: 85.073,20.748 85.073,20.747 85.108,20.733 85.146,20.717 85.145,20.715 85.154,20.711 85.168,20.678 85.176,20.657 85.177,20.657 85.187,20.633 85.187,20.632 85.176,20.632 85.176,20.426 85.114,20.426 85.12,20.61 85.12,20.612 85.109,20.638 85.099,20.663 85.076,20.673 85.053,20.682 85.052,20.682 85.053,20.682 85.052,20.682 85.028,20.673 85.005,20.663 84.995,20.638 84.984,20.612 84.984,20.61 84.991,20.61 84.991,20.426 84.928,20.426 84.928,20.736 84.991,20.736 84.991,20.709 84.994,20.717 85.027,20.73 85.071,20.749 hole: 84.991,20.709 84.989,20.705 84.991,20.703
  region: 86.213,20.426 86.15,20.426 86.15,20.453 86.147,20.444 86.115,20.431 86.071,20.413 86.069,20.414 86.033,20.429 85.995,20.445 85.996,20.446 85.987,20.45 85.973,20.483 85.965,20.504 85.964,20.504 85.953,20.529 85.954,20.53 85.965,20.53 85.965,20.736 86.027,20.736 86.021,20.551 86.02,20.549 86.032,20.523 86.042,20.498 86.065,20.488 86.088,20.479 86.089,20.479 86.09,20.479 86.113,20.488 86.136,20.498 86.146,20.523 86.157,20.549 86.157,20.551 86.15,20.551 86.15,20.736 86.213,20.736 hole: 86.15,20.458 86.15,20.453 86.152,20.456
  region: 86.627,20.751 86.628,20.751 86.661,20.737 86.691,20.725 86.733,20.697 86.74,20.687 86.739,20.686 86.696,20.647 86.691,20.658 86.664,20.669 86.63,20.683 86.63,20.684 86.628,20.685 86.594,20.671 86.569,20.661 86.567,20.655 86.553,20.623 86.554,20.623 86.546,20.583 86.546,20.58 86.546,20.578 86.554,20.538 86.553,20.538 86.567,20.506 86.569,20.501 86.594,20.49 86.628,20.476 86.63,20.477 86.63,20.478 86.664,20.492 86.69,20.503 86.695,20.515 86.74,20.475 86.733,20.465 86.691,20.436 86.691,20.437 86.661,20.424 86.628,20.41 86.627,20.41 86.576,20.431 86.575,20.429 86.571,20.43 86.529,20.458 86.527,20.455 86.518,20.458 86.509,20.479 86.497,20.507 86.496,20.507 86.489,20.541 86.481,20.579 86.482,20.58 86.481,20.582 86.489,20.62 86.496,20.654 86.497,20.654 86.509,20.682 86.518,20.703 86.527,20.706 86.529,20.703 86.572,20.732 86.575,20.732 86.576,20.73 86.627,20.751
  region: 85.083,20.254 85.083,20.253 85.117,20.24 85.151,20.225 85.148,20.222 85.105,20.17 85.083,20.179 85.062,20.188 85.018,20.17 85.019,20.17 85.014,20.168 85.006,20.148 84.995,20.12 84.995,20.118 85.001,20.118 85.001,19.932 84.939,19.932 84.939,20.242 85.001,20.242 85.001,20.215 85.005,20.223 85.037,20.236 85.081,20.255 hole: 85.001,20.215 85,20.211 85.001,20.209
  region: 86.349,20.254 86.349,20.253 86.382,20.24 86.417,20.225 86.414,20.222 86.37,20.17 86.348,20.179 86.327,20.188 86.283,20.17 86.284,20.17 86.28,20.168 86.272,20.148 86.271,20.148 86.26,20.12 86.261,20.118 86.267,20.118 86.267,19.932 86.205,19.932 86.205,20.242 86.267,20.242 86.267,20.215 86.27,20.223 86.303,20.236 86.347,20.255 hole: 86.267,20.215 86.265,20.211 86.267,20.209
  region: 86.428,20.748 86.428,20.747 86.461,20.734 86.496,20.719 86.493,20.715 86.449,20.664 86.427,20.673 86.406,20.682 86.363,20.664 86.363,20.663 86.359,20.662 86.351,20.642 86.339,20.614 86.34,20.612 86.346,20.612 86.346,20.426 86.284,20.426 86.284,20.736 86.346,20.736 86.346,20.709 86.349,20.717 86.382,20.73 86.426,20.749 hole: 86.346,20.709 86.344,20.705 86.346,20.703
  region: 84.447,20.477 84.447,20.484
  region: 85.276,20.183 85.276,20.19
  region: 85.367,23.08 85.651,23.081 85.663,23.076 85.666,23.068 85.72,22.789 85.723,22.78 85.729,22.778 85.962,22.681 85.968,22.679 85.977,22.683 85.976,22.683 86.211,22.842 86.22,22.846 86.231,22.841 86.23,22.84 86.432,22.64 86.437,22.629 86.433,22.62 86.274,22.385 86.27,22.377 86.273,22.371 86.369,22.138 86.372,22.132 86.38,22.128 86.38,22.129 86.659,22.075 86.668,22.072 86.672,22.06 86.671,22.06 86.672,21.776 86.668,21.765 86.659,21.761 86.38,21.708 86.372,21.704 86.369,21.699 86.273,21.465 86.27,21.459 86.274,21.451 86.433,21.216 86.437,21.208 86.432,21.196 86.431,21.197 86.231,20.995 86.22,20.99 86.211,20.994 85.977,21.154 85.968,21.157 85.962,21.155 85.855,21.11 85.85,21.108 85.838,21.113 85.836,21.119 85.639,21.601 85.637,21.606 85.641,21.618 85.647,21.62 85.648,21.616 85.746,21.681 85.819,21.79 85.844,21.918 85.819,22.046 85.746,22.155 85.637,22.227 85.509,22.253 85.381,22.227 85.273,22.155 85.2,22.046 85.175,21.918 85.2,21.79 85.273,21.681 85.37,21.616 85.372,21.62 85.377,21.618 85.382,21.606 85.38,21.601 85.183,21.119 85.181,21.113 85.169,21.108 85.163,21.11 85.056,21.155 85.051,21.157 85.042,21.154 85.042,21.153 84.807,20.994 84.799,20.99 84.787,20.995 84.788,20.996 84.586,21.196 84.582,21.208 84.585,21.216 84.745,21.451 84.748,21.459 84.746,21.465 84.649,21.699 84.647,21.704 84.638,21.708 84.36,21.761 84.351,21.765 84.346,21.776 84.347,21.776 84.346,22.06 84.351,22.072 84.36,22.075 84.638,22.128 84.647,22.132 84.649,22.138 84.746,22.371 84.748,22.377 84.745,22.385 84.585,22.62 84.582,22.629 84.586,22.64 84.587,22.639 84.787,22.841 84.799,22.846 84.807,22.842 85.042,22.683 85.051,22.679 85.056,22.681 85.29,22.778 85.296,22.78 85.299,22.789 85.352,23.068 85.356,23.076 85.367,23.081

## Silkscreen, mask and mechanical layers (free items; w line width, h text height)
Top Overlay:
  drawing of 283 lines, arcs and shapes, not listed
Mechanical 1:
  the board outline again, w0.254
Drill Drawing:
  text ".Legend" at 91.186,19.177 h1.52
